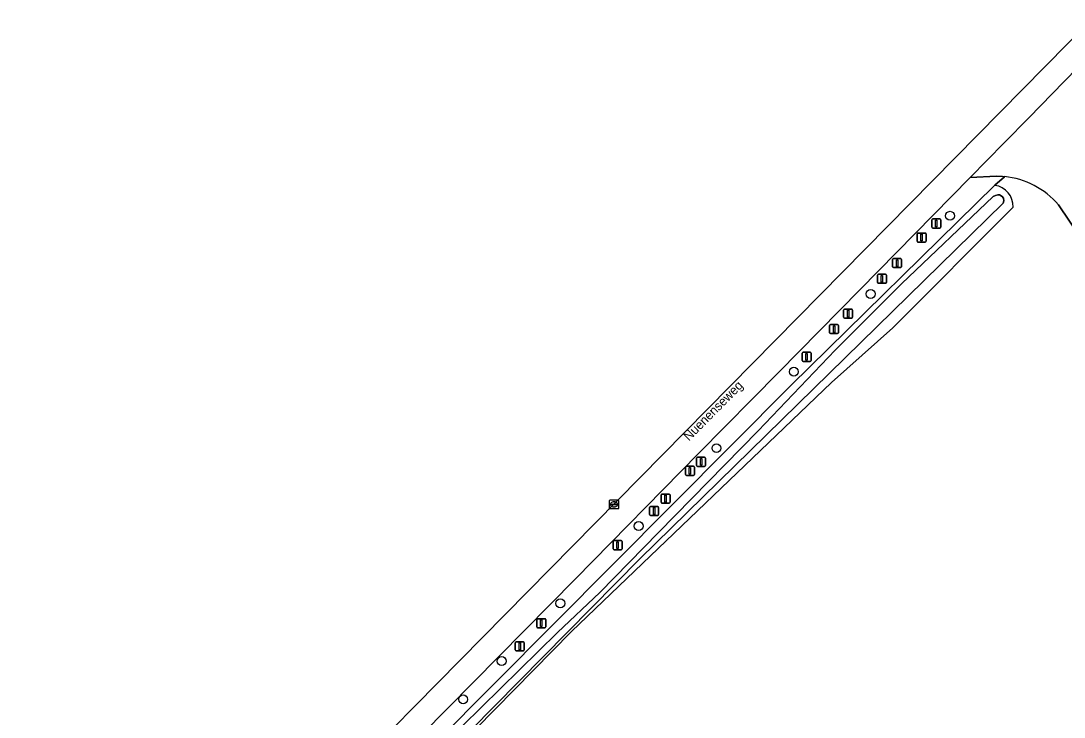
# Model space of a CAD drawing. Extents: x 162788 to 163838, y 385791 to 386523.
# Drawn here: x 163028.4 to 163143.1, y 386366.1 to 386442.7 of the extents above; entities that cross this region are included whole.
import ezdxf

# ---------------------------------------------------------------- set-up
doc = ezdxf.new("R2010")
doc.units = 0
for name, color, linetype in [('IMGEO_Afsluitpaal', 7, 'Continuous'), ('IMGEO_Boom', 7, 'Continuous'), ('IMGEO_Erf', 7, 'Continuous'), ('IMGEO_Groenvoorziening', 7, 'Continuous'), ('IMGEO_Oever', 7, 'Continuous'), ('IMGEO_Openbare_ruimte_label', 7, 'Continuous'), ('IMGEO_Rijbaan_lokaal_open', 7, 'Continuous'), ('IMGEO_Rioolput', 7, 'Continuous'), ('IMGEO_Waterloop', 7, 'Continuous'), ('IMGEO_Woonerf_open', 7, 'Continuous')]:
    doc.layers.add(name, color=color, linetype=linetype)

msp = doc.modelspace()

# ---------------------------------------------------------------- linework, layer by layer
at = {"layer": 'IMGEO_Afsluitpaal'}
for p, q in [((163128.56, 386419.97), (163128.56, 386420.77)), ((163128.56, 386420.77), (163128.56, 386419.97)), ((163128.66, 386420.87), (163129.45, 386420.87)), ((163129.45, 386420.87), (163128.66, 386420.87)), ((163129.55, 386420.77), (163129.55, 386419.97)), ((163129.55, 386419.97), (163129.55, 386420.77)), ((163126.94, 386418.42), (163126.94, 386419.22)), ((163126.94, 386419.22), (163126.94, 386418.42)), ((163127.04, 386419.32), (163127.83, 386419.32)), ((163127.83, 386419.32), (163127.04, 386419.32)), ((163127.93, 386419.22), (163127.93, 386418.42)), ((163127.93, 386418.42), (163127.93, 386419.22)), ((163129.45, 386419.87), (163128.66, 386419.87)), ((163128.66, 386419.87), (163129.45, 386419.87)), ((163127.83, 386418.32), (163127.04, 386418.32)), ((163127.04, 386418.32), (163127.83, 386418.32)), ((163124.25, 386415.62), (163124.25, 386416.42)), ((163124.25, 386416.42), (163124.25, 386415.62)), ((163124.35, 386416.52), (163125.14, 386416.52)), ((163125.14, 386416.52), (163124.35, 386416.52)), ((163125.24, 386416.42), (163125.24, 386415.62)), ((163125.24, 386415.62), (163125.24, 386416.42)), ((163122.59, 386413.89), (163122.59, 386414.69)), ((163122.59, 386414.69), (163122.59, 386413.89)), ((163122.69, 386414.79), (163123.48, 386414.79)), ((163123.48, 386414.79), (163122.69, 386414.79)), ((163123.58, 386414.69), (163123.58, 386413.89)), ((163123.58, 386413.89), (163123.58, 386414.69)), ((163125.14, 386415.52), (163124.35, 386415.52)), ((163124.35, 386415.52), (163125.14, 386415.52)), ((163123.48, 386413.79), (163122.69, 386413.79)), ((163122.69, 386413.79), (163123.48, 386413.79)), ((163118.87, 386410.05), (163118.87, 386410.85)), ((163118.87, 386410.85), (163118.87, 386410.05)), ((163118.97, 386410.95), (163119.76, 386410.95)), ((163119.76, 386410.95), (163118.97, 386410.95)), ((163119.76, 386409.95), (163118.97, 386409.95)), ((163118.97, 386409.95), (163119.76, 386409.95)), ((163119.86, 386410.85), (163119.86, 386410.05)), ((163119.86, 386410.05), (163119.86, 386410.85)), ((163117.32, 386408.36), (163117.32, 386409.16)), ((163117.32, 386409.16), (163117.32, 386408.36)), ((163117.42, 386409.26), (163118.21, 386409.26)), ((163118.21, 386409.26), (163117.42, 386409.26)), ((163118.31, 386409.16), (163118.31, 386408.36)), ((163118.31, 386408.36), (163118.31, 386409.16)), ((163118.21, 386408.26), (163117.42, 386408.26)), ((163117.42, 386408.26), (163118.21, 386408.26)), ((163114.3, 386405.3), (163114.3, 386406.1)), ((163114.3, 386406.1), (163114.3, 386405.3)), ((163114.4, 386406.2), (163115.19, 386406.2)), ((163115.19, 386406.2), (163114.4, 386406.2)), ((163115.29, 386406.1), (163115.29, 386405.3)), ((163115.29, 386405.3), (163115.29, 386406.1)), ((163115.19, 386405.2), (163114.4, 386405.2)), ((163114.4, 386405.2), (163115.19, 386405.2)), ((163102.69, 386393.76), (163102.69, 386394.56)), ((163102.69, 386394.56), (163102.69, 386393.76)), ((163102.79, 386394.66), (163103.58, 386394.66)), ((163103.58, 386394.66), (163102.79, 386394.66)), ((163103.68, 386394.56), (163103.68, 386393.76)), ((163103.68, 386393.76), (163103.68, 386394.56)), ((163101.47, 386392.77), (163101.47, 386393.57)), ((163101.47, 386393.57), (163101.47, 386392.77)), ((163101.57, 386393.67), (163102.36, 386393.67)), ((163102.36, 386393.67), (163101.57, 386393.67)), ((163102.36, 386392.67), (163101.57, 386392.67)), ((163101.57, 386392.67), (163102.36, 386392.67)), ((163102.46, 386393.57), (163102.46, 386392.77)), ((163102.46, 386392.77), (163102.46, 386393.57)), ((163103.58, 386393.66), (163102.79, 386393.66)), ((163102.79, 386393.66), (163103.58, 386393.66)), ((163098.78, 386389.71), (163098.78, 386390.51)), ((163098.78, 386390.51), (163098.78, 386389.71)), ((163098.88, 386390.61), (163099.67, 386390.61)), ((163099.67, 386390.61), (163098.88, 386390.61)), ((163099.77, 386390.51), (163099.77, 386389.71)), ((163099.77, 386389.71), (163099.77, 386390.51)), ((163097.63, 386389.25), (163098.42, 386389.25)), ((163098.42, 386389.25), (163097.63, 386389.25)), ((163099.67, 386389.61), (163098.88, 386389.61)), ((163098.88, 386389.61), (163099.67, 386389.61)), ((163097.53, 386388.35), (163097.53, 386389.15)), ((163097.53, 386389.15), (163097.53, 386388.35)), ((163098.42, 386388.25), (163097.63, 386388.25)), ((163097.63, 386388.25), (163098.42, 386388.25)), ((163098.52, 386389.15), (163098.52, 386388.35)), ((163098.52, 386388.35), (163098.52, 386389.15)), ((163093.51, 386384.59), (163093.51, 386385.39)), ((163093.51, 386385.39), (163093.51, 386384.59)), ((163093.61, 386385.49), (163094.4, 386385.49)), ((163094.4, 386385.49), (163093.61, 386385.49)), ((163094.5, 386385.39), (163094.5, 386384.59)), ((163094.5, 386384.59), (163094.5, 386385.39)), ((163094.4, 386384.49), (163093.61, 386384.49)), ((163093.61, 386384.49), (163094.4, 386384.49)), ((163085.11, 386376), (163085.11, 386376.8)), ((163085.11, 386376.8), (163085.11, 386376)), ((163085.21, 386376.9), (163086, 386376.9)), ((163086, 386376.9), (163085.21, 386376.9)), ((163086.1, 386376.8), (163086.1, 386376)), ((163086.1, 386376), (163086.1, 386376.8)), ((163086, 386375.9), (163085.21, 386375.9)), ((163085.21, 386375.9), (163086, 386375.9)), ((163082.85, 386374.36), (163083.64, 386374.36)), ((163083.64, 386374.36), (163082.85, 386374.36)), ((163082.75, 386373.46), (163082.75, 386374.26)), ((163082.75, 386374.26), (163082.75, 386373.46)), ((163083.64, 386373.36), (163082.85, 386373.36)), ((163082.85, 386373.36), (163083.64, 386373.36)), ((163083.74, 386374.26), (163083.74, 386373.46)), ((163083.74, 386373.46), (163083.74, 386374.26))]:
    msp.add_line(p, q, dxfattribs=at)
for points in [[(163128.98, 386420.74), (163129.13, 386420.74), (163129.13, 386419.99), (163128.98, 386419.99), (163128.98, 386420.74)], [(163127.36, 386419.2), (163127.51, 386419.2), (163127.51, 386418.45), (163127.36, 386418.45), (163127.36, 386419.2)], [(163124.67, 386416.39), (163124.82, 386416.39), (163124.82, 386415.64), (163124.67, 386415.64), (163124.67, 386416.39)], [(163123.01, 386414.66), (163123.16, 386414.66), (163123.16, 386413.91), (163123.01, 386413.91), (163123.01, 386414.66)], [(163119.29, 386410.83), (163119.44, 386410.83), (163119.44, 386410.08), (163119.29, 386410.08), (163119.29, 386410.83)], [(163117.74, 386409.13), (163117.89, 386409.13), (163117.89, 386408.38), (163117.74, 386408.38), (163117.74, 386409.13)], [(163114.72, 386406.07), (163114.87, 386406.07), (163114.87, 386405.32), (163114.72, 386405.32), (163114.72, 386406.07)], [(163103.11, 386394.54), (163103.26, 386394.54), (163103.26, 386393.79), (163103.11, 386393.79), (163103.11, 386394.54)], [(163101.89, 386393.54), (163102.04, 386393.54), (163102.04, 386392.79), (163101.89, 386392.79), (163101.89, 386393.54)], [(163099.2, 386390.48), (163099.35, 386390.48), (163099.35, 386389.73), (163099.2, 386389.73), (163099.2, 386390.48)], [(163097.95, 386389.12), (163098.1, 386389.12), (163098.1, 386388.37), (163097.95, 386388.37), (163097.95, 386389.12)], [(163093.93, 386385.36), (163094.08, 386385.36), (163094.08, 386384.61), (163093.93, 386384.61), (163093.93, 386385.36)], [(163085.53, 386376.78), (163085.68, 386376.78), (163085.68, 386376.03), (163085.53, 386376.03), (163085.53, 386376.78)], [(163083.17, 386374.23), (163083.32, 386374.23), (163083.32, 386373.48), (163083.17, 386373.48), (163083.17, 386374.23)]]:
    msp.add_lwpolyline(points, dxfattribs=at)
for centre, start, end in [((163128.66, 386420.77), 90, 180), ((163128.66, 386420.77), 90, 180), ((163129.45, 386420.77), 0, 90), ((163129.45, 386420.77), 360, 90), ((163127.04, 386419.22), 90, 180), ((163127.04, 386419.22), 90, 180), ((163127.83, 386419.22), 0, 90), ((163127.83, 386419.22), 360, 90), ((163128.66, 386419.97), 180, 270), ((163128.66, 386419.97), 180, 270), ((163129.45, 386419.97), 270, 0), ((163129.45, 386419.97), 270, 0), ((163127.04, 386418.42), 180, 270), ((163127.04, 386418.42), 180, 270), ((163127.83, 386418.42), 270, 0), ((163127.83, 386418.42), 270, 0), ((163124.35, 386416.42), 90, 180), ((163124.35, 386416.42), 90, 180), ((163124.35, 386415.62), 180, 270), ((163124.35, 386415.62), 180, 270), ((163125.14, 386416.42), 0, 90), ((163125.14, 386416.42), 360, 90), ((163125.14, 386415.62), 270, 0), ((163125.14, 386415.62), 270, 0), ((163122.69, 386414.69), 90, 180), ((163122.69, 386414.69), 90, 180), ((163123.48, 386414.69), 0, 90), ((163123.48, 386414.69), 360, 90), ((163122.69, 386413.89), 180, 270), ((163122.69, 386413.89), 180, 270), ((163123.48, 386413.89), 270, 0), ((163123.48, 386413.89), 270, 0), ((163118.97, 386410.85), 90, 180), ((163118.97, 386410.85), 90, 180), ((163118.97, 386410.05), 180, 270), ((163118.97, 386410.05), 180, 270), ((163119.76, 386410.85), 0, 90), ((163119.76, 386410.85), 360, 90), ((163119.76, 386410.05), 270, 0), ((163119.76, 386410.05), 270, 0), ((163117.42, 386409.16), 90, 180), ((163117.42, 386409.16), 90, 180), ((163118.21, 386409.16), 0, 90), ((163118.21, 386409.16), 360, 90), ((163117.42, 386408.36), 180, 270), ((163117.42, 386408.36), 180, 270), ((163118.21, 386408.36), 270, 0), ((163118.21, 386408.36), 270, 0), ((163114.4, 386406.1), 90, 180), ((163114.4, 386406.1), 90, 180), ((163114.4, 386405.3), 180, 270), ((163114.4, 386405.3), 180, 270), ((163115.19, 386406.1), 0, 90), ((163115.19, 386406.1), 360, 90), ((163115.19, 386405.3), 270, 0), ((163115.19, 386405.3), 270, 0), ((163102.79, 386394.56), 90, 180), ((163102.79, 386394.56), 90, 180), ((163103.58, 386394.56), 0, 90), ((163103.58, 386394.56), 360, 90), ((163101.57, 386393.57), 90, 180), ((163101.57, 386393.57), 90, 180), ((163101.57, 386392.77), 180, 270), ((163101.57, 386392.77), 180, 270), ((163102.36, 386393.57), 0, 90), ((163102.36, 386393.57), 360, 90), ((163102.36, 386392.77), 270, 0), ((163102.36, 386392.77), 270, 0), ((163102.79, 386393.76), 180, 270), ((163102.79, 386393.76), 180, 270), ((163103.58, 386393.76), 270, 0), ((163103.58, 386393.76), 270, 0), ((163098.88, 386390.51), 90, 180), ((163098.88, 386390.51), 90, 180), ((163099.67, 386390.51), 0, 90), ((163099.67, 386390.51), 360, 90), ((163097.63, 386389.15), 90, 180), ((163097.63, 386389.15), 90, 180), ((163098.42, 386389.15), 0, 90), ((163098.42, 386389.15), 360, 90), ((163098.88, 386389.71), 180, 270), ((163098.88, 386389.71), 180, 270), ((163099.67, 386389.71), 270, 0), ((163099.67, 386389.71), 270, 0), ((163097.63, 386388.35), 180, 270), ((163097.63, 386388.35), 180, 270), ((163098.42, 386388.35), 270, 0), ((163098.42, 386388.35), 270, 0), ((163093.61, 386385.39), 90, 180), ((163093.61, 386385.39), 90, 180), ((163094.4, 386385.39), 0, 90), ((163094.4, 386385.39), 360, 90), ((163093.61, 386384.59), 180, 270), ((163093.61, 386384.59), 180, 270), ((163094.4, 386384.59), 270, 0), ((163094.4, 386384.59), 270, 0), ((163085.21, 386376.8), 90, 180), ((163085.21, 386376.8), 90, 180), ((163086, 386376.8), 0, 90), ((163086, 386376.8), 360, 90), ((163085.21, 386376), 180, 270), ((163085.21, 386376), 180, 270), ((163086, 386376), 270, 0), ((163086, 386376), 270, 0), ((163082.85, 386374.26), 90, 180), ((163082.85, 386374.26), 90, 180), ((163083.64, 386374.26), 0, 90), ((163083.64, 386374.26), 360, 90), ((163082.85, 386373.46), 180, 270), ((163082.85, 386373.46), 180, 270), ((163083.64, 386373.46), 270, 0), ((163083.64, 386373.46), 270, 0)]:
    msp.add_arc(centre, 0.1, start, end, dxfattribs=at)
at = {"layer": 'IMGEO_Boom'}
for centre in [(163130.57, 386421.22), (163121.84, 386412.62), (163113.39, 386404.07), (163104.88, 386395.66), (163096.32, 386387.09), (163087.71, 386378.59), (163081.25, 386372.24), (163077.02, 386368.03)]:
    msp.add_circle(centre, 0.489, dxfattribs=at)
at = {"layer": 'IMGEO_Erf'}
for points in [[(163136.56, 386425.52), (163135.49, 386424.57)], [(163137.51, 386422.15), (163124.27, 386408.89), (163117.54, 386402.88), (163088.92, 386375.51), (163061.65, 386347.74), (163037.47, 386323.98), (163037.35, 386323.86), (163037.13, 386323.63), (163035.61, 386322.08), (163032.82, 386319.24)], [(163189.47, 386351.45), (163174.34, 386374.85), (163166.31, 386386.55), (163158.23, 386399.07), (163142.49, 386422.41)]]:
    msp.add_lwpolyline(points, dxfattribs=at)
for centre, radius, start, end in [((163135.73, 386416.71), 8.85, 40.1255, 84.6265), ((163135.15, 386422.23), 2.36, 358.039, 81.6094)]:
    msp.add_arc(centre, radius, start, end, dxfattribs=at)
at = {"layer": 'IMGEO_Groenvoorziening'}
for points in [[(163135.69, 386425.56), (163132.8, 386425.42), (163120.64, 386413.08), (163111.75, 386404.01), (163102.91, 386395.06), (163089.39, 386381.29), (163072.52, 386364.21), (163061.91, 386353.55), (163033.25, 386324.39), (163035.02, 386322.65), (163035.61, 386322.08), (163037.13, 386323.63), (163037.35, 386323.86), (163037.08, 386323.91), (163036.81, 386323.98), (163036.56, 386324.12), (163036.51, 386324.17), (163036.36, 386324.32), (163036.23, 386324.63), (163036.26, 386324.83), (163036.37, 386325.09), (163047.78, 386336.92), (163113.11, 386402.59)], [(163113.11, 386402.59), (163135.49, 386424.57), (163136.56, 386425.52)]]:
    msp.add_lwpolyline(points, dxfattribs=at)
msp.add_arc((163135.72, 386416.51), 9.04, 84.6734, 90.1932, dxfattribs=at)
at = {"layer": 'IMGEO_Oever'}
for points in [[(163135.49, 386424.57), (163113.11, 386402.59), (163047.78, 386336.92), (163036.37, 386325.09), (163036.26, 386324.83), (163036.23, 386324.63), (163036.36, 386324.32), (163036.51, 386324.17), (163036.56, 386324.12), (163036.81, 386323.98), (163037.08, 386323.91), (163037.35, 386323.86), (163037.47, 386323.98), (163061.65, 386347.74), (163088.92, 386375.51), (163117.54, 386402.88)], [(163076.93, 386365.13), (163087.4, 386375.4), (163092.04, 386379.77), (163098.52, 386386.4), (163109.47, 386397.58), (163117.95, 386406.42), (163125.22, 386413.72), (163135.3, 386423.33), (163135.56, 386423.45), (163135.82, 386423.52), (163136.02, 386423.51), (163136.32, 386423.34), (163136.46, 386423.15), (163136.49, 386422.86), (163136.43, 386422.59), (163096.46, 386383.48), (163075.17, 386361.92)], [(163117.54, 386402.88), (163124.27, 386408.89), (163137.51, 386422.15)]]:
    msp.add_lwpolyline(points, dxfattribs=at)
msp.add_arc((163135.15, 386422.23), 2.36, 358.039, 81.6094, dxfattribs=at)
at = {"layer": 'IMGEO_Rijbaan_lokaal_open'}
for points in [[(163145.97, 386442.66), (162995, 386289.48)], [(163024.51, 386315.49), (163032.8, 386323.92), (163033.25, 386324.39), (163061.91, 386353.55), (163072.52, 386364.21), (163089.39, 386381.29), (163102.91, 386395.06), (163111.75, 386404.01), (163120.64, 386413.08), (163132.8, 386425.42), (163136.54, 386429.25), (163139.27, 386432.04), (163143.08, 386435.96), (163144.71, 386437.6)]]:
    msp.add_lwpolyline(points, dxfattribs=at)
at = {"layer": 'IMGEO_Rioolput'}
for p, q in [((163093.11, 386389.04), (163093.11, 386389.9)), ((163093.18, 386389.97), (163094.04, 386389.97)), ((163093.37, 386389.46), (163093.37, 386389.48)), ((163093.41, 386389.51), (163093.81, 386389.51)), ((163093.81, 386389.43), (163093.41, 386389.43)), ((163093.6, 386389.75), (163093.62, 386389.75)), ((163093.85, 386389.48), (163093.85, 386389.46)), ((163094.11, 386389.9), (163094.11, 386389.04)), ((163094.04, 386388.97), (163093.18, 386388.97)), ((163093.62, 386389.19), (163093.6, 386389.19))]:
    msp.add_line(p, q, dxfattribs=at)
for points in [[(163093.11, 386389.04), (163093.11, 386389.9)], [(163093.18, 386389.97), (163094.04, 386389.97)], [(163094.11, 386389.9), (163094.11, 386389.04)], [(163094.04, 386388.97), (163093.18, 386388.97)]]:
    msp.add_lwpolyline(points, dxfattribs=at)
for centre, radius, start, end in [((163093.19, 386389.89), 0.0765, 91.552, 178.448), ((163093.19, 386389.89), 0.0765, 91.552, 178.448), ((163093.41, 386389.47), 0.0403, 85.8775, 175.7526), ((163093.41, 386389.46), 0.0366, 178.938, 274.7102), ((163093.81, 386389.47), 0.0386, 1.7309, 96.639), ((163093.81, 386389.47), 0.043, 264.8664, 352.4533), ((163094.03, 386389.89), 0.0765, 1.552, 88.448), ((163094.03, 386389.89), 0.0765, 1.552, 88.448), ((163093.19, 386389.04), 0.0765, 181.552, 268.448), ((163093.19, 386389.04), 0.0765, 181.552, 268.448), ((163094.03, 386389.04), 0.0765, 271.552, 358.448), ((163094.03, 386389.04), 0.0765, 271.552, 358.448)]:
    msp.add_arc(centre, radius, start, end, dxfattribs=at)
for centre, major_axis, ratio, start_param, end_param in [((163093.6, 386389.47), (-0.387, 0.002), 0.722429, 4.712389, 7.853982), ((163093.62, 386389.47), (-0.39, 0.002), 0.717154, 1.570796, 4.712389)]:
    msp.add_ellipse(centre, major_axis=major_axis, ratio=ratio, start_param=start_param, end_param=end_param, dxfattribs=at)
at = {"layer": 'IMGEO_Waterloop'}
msp.add_lwpolyline([(163075.17, 386361.92), (163096.46, 386383.48), (163136.43, 386422.59), (163136.49, 386422.86), (163136.46, 386423.15), (163136.32, 386423.34), (163136.02, 386423.51), (163135.82, 386423.52), (163135.56, 386423.45), (163135.3, 386423.33), (163125.22, 386413.72), (163117.95, 386406.42), (163109.47, 386397.58), (163098.52, 386386.4), (163092.04, 386379.77), (163087.4, 386375.4), (163076.93, 386365.13)], dxfattribs=at)
at = {"layer": 'IMGEO_Woonerf_open'}
for points in [[(163144.71, 386437.6), (163143.08, 386435.96), (163139.27, 386432.04), (163136.54, 386429.25), (163132.8, 386425.42), (163135.69, 386425.56)], [(163142.49, 386422.41), (163158.23, 386399.07), (163166.31, 386386.55), (163174.34, 386374.85), (163189.47, 386351.45)]]:
    msp.add_lwpolyline(points, dxfattribs=at)
for centre, radius, start, end in [((163135.72, 386416.51), 9.04, 84.6734, 90.1932), ((163135.73, 386416.71), 8.85, 40.1255, 84.6265)]:
    msp.add_arc(centre, radius, start, end, dxfattribs=at)

# ---------------------------------------------------------------- texts
at = {"layer": 'IMGEO_Openbare_ruimte_label'}
msp.add_text('Nuenenseweg', height=1, rotation=45.3242, dxfattribs=at).set_placement((163101.86, 386396.39))

doc.saveas('drawing.dxf')
